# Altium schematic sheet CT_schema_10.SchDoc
size 387 x 278 mm
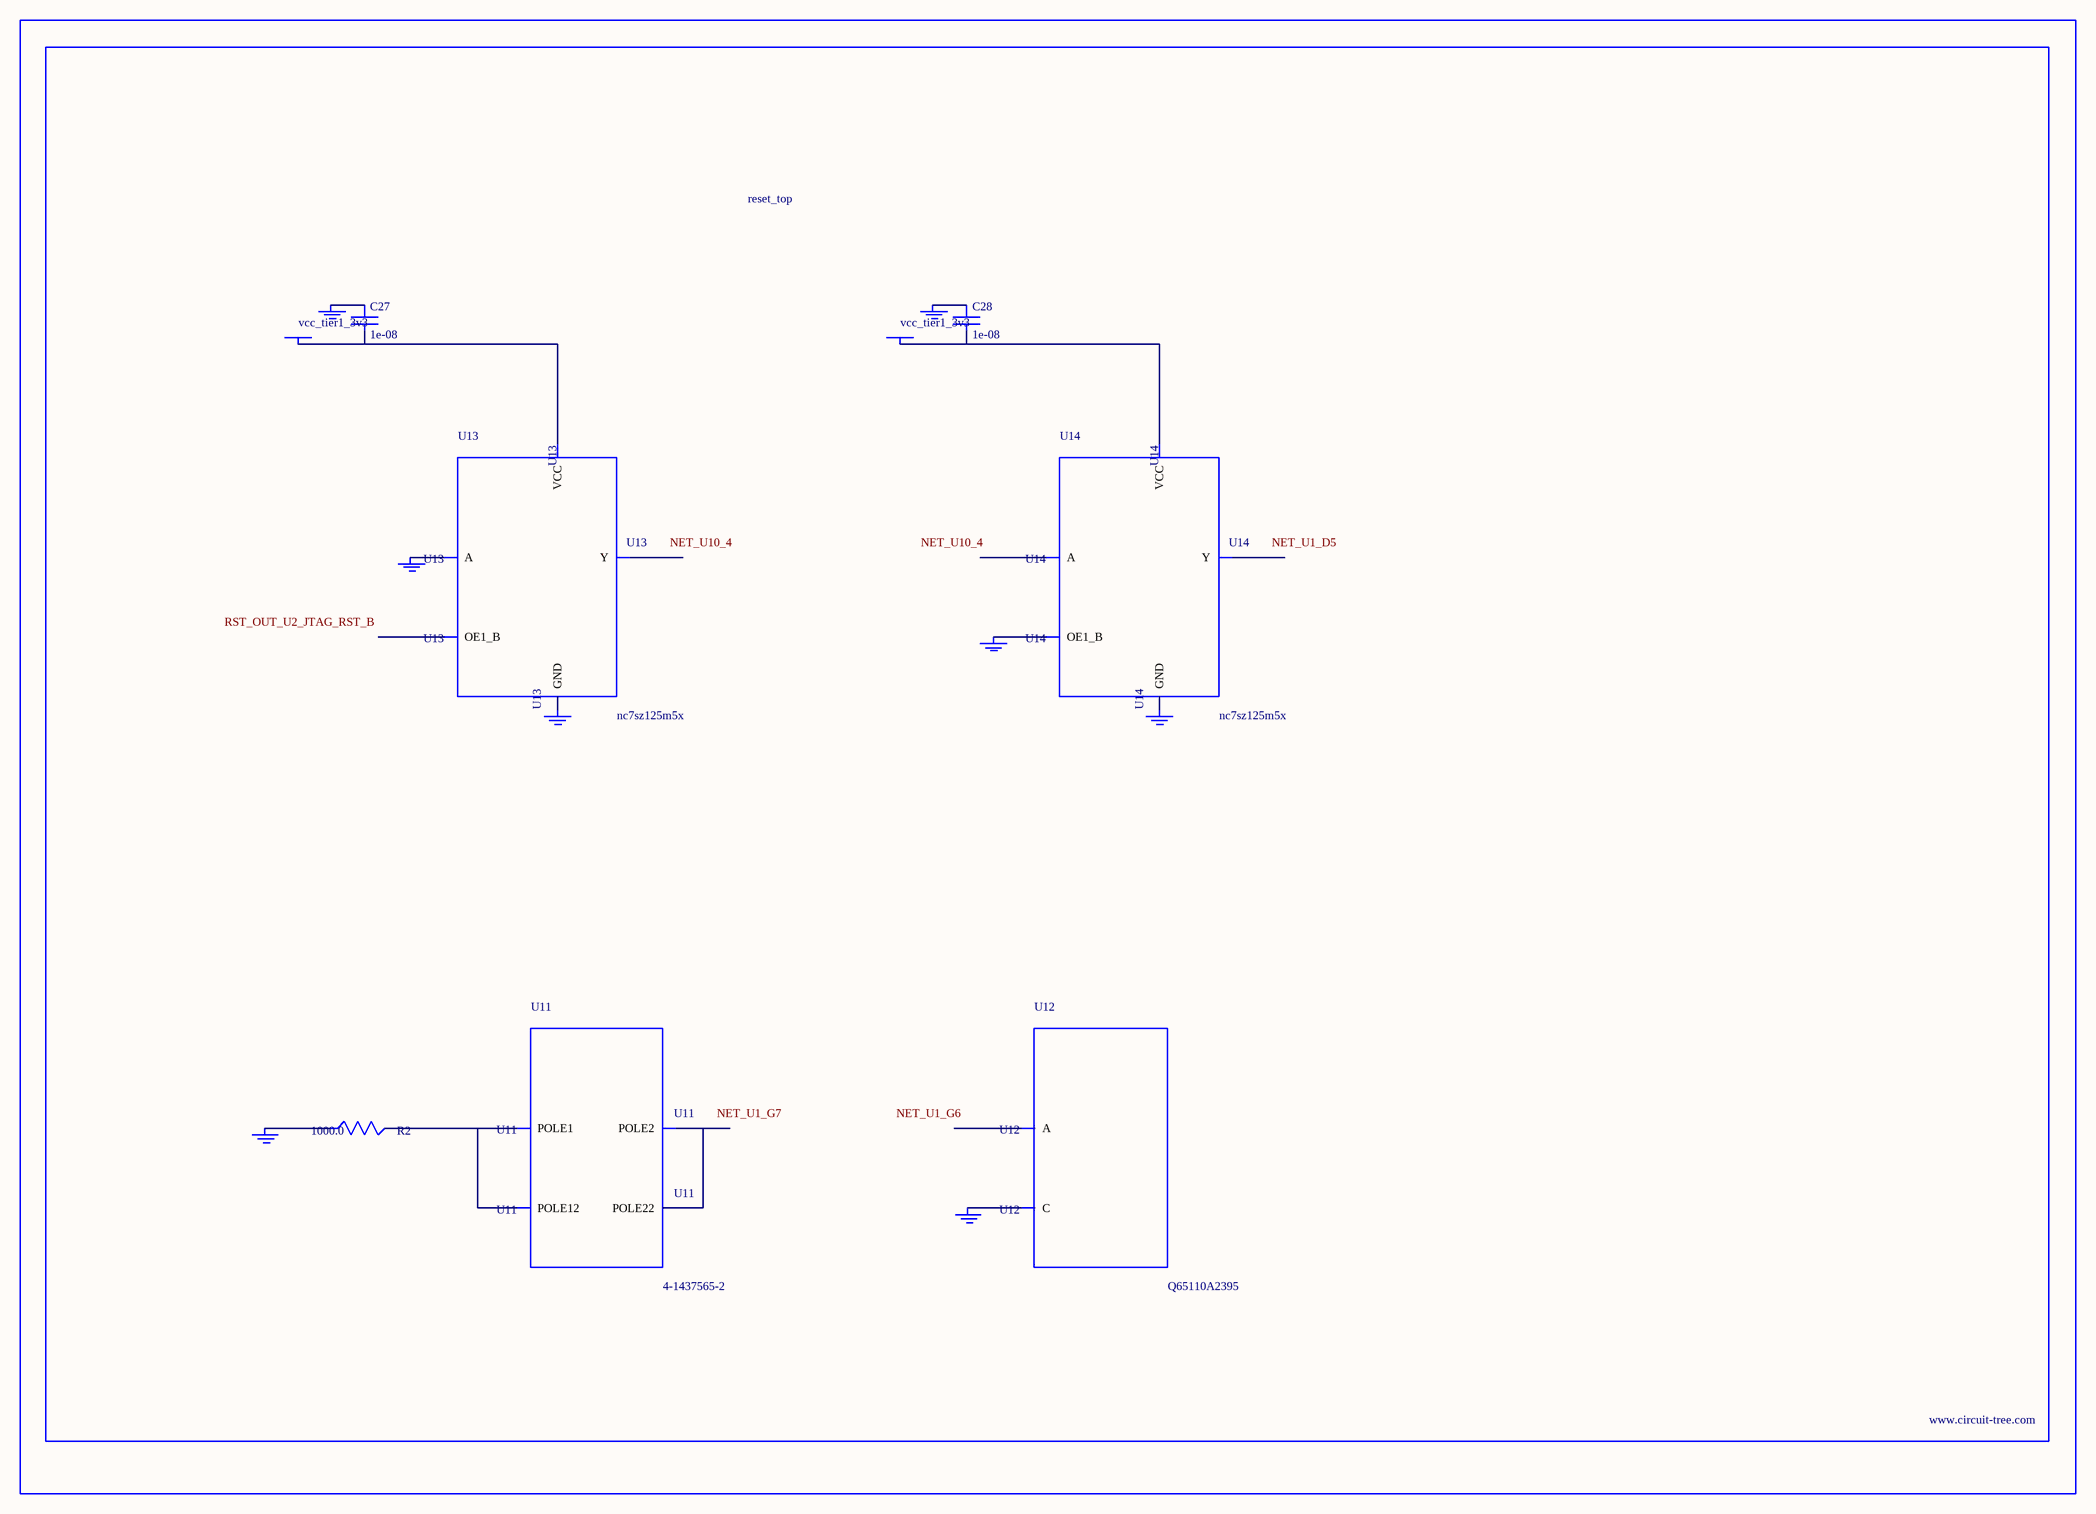
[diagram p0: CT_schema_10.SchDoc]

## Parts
BORDER9  (no value)
C27  1e-08  [C0402]
C28  1e-08  [C0402]
GND_INSTANCE_9_0  (no value)
GND_INSTANCE_9_1  (no value)
GND_INSTANCE_9_2  (no value)
GND_INSTANCE_9_3  (no value)
GND_INSTANCE_9_4  (no value)
GND_INSTANCE_9_5  (no value)
GND_INSTANCE_9_6  (no value)
GND_INSTANCE_9_7  (no value)
POWER_INSTANCE_9_0  vcc_tier1_3v3
POWER_INSTANCE_9_1  vcc_tier1_3v3
R2  1000.0  [R0603]
U11  4-1437565-2  [SW_4-1437565-2]
U12  Q65110A2395  [LGM67K-G1J2-24-Z]
U13  nc7sz125m5x  [NC7SZ125M5X]
U14  nc7sz125m5x  [NC7SZ125M5X]

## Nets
NetC27_1: C27.1 GND_INSTANCE_9_2.0(GND)
NetC27_2: C27.2 POWER_INSTANCE_9_0.0(PWR) U13.5(VCC)
NetC28_1: C28.1 GND_INSTANCE_9_5.0(GND)
NetC28_2: C28.2 POWER_INSTANCE_9_1.0(PWR) U14.5(VCC)
NetGND_INSTANCE_9_0_0: GND_INSTANCE_9_0.0(GND) R2.1
NetGND_INSTANCE_9_1_0: GND_INSTANCE_9_1.0(GND) U12.C
NetGND_INSTANCE_9_3_0: GND_INSTANCE_9_3.0(GND) U13.2(A)
NetGND_INSTANCE_9_4_0: GND_INSTANCE_9_4.0(GND) U13.3(GND)
NetGND_INSTANCE_9_6_0: GND_INSTANCE_9_6.0(GND) U14.1(OE1_B)
NetGND_INSTANCE_9_7_0: GND_INSTANCE_9_7.0(GND) U14.3(GND)
NetR2_2: R2.2 U11.1(POLE1) U11.2(POLE12)
NetU11_3: U11.3(POLE2) U11.4(POLE22)

Not connected (* = marked no-connect by the designer): U12 A; U13 1(OE1_B) 4(Y); U14 2(A) 4(Y)

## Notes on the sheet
- Labels drawn without touching a wire or pin: NET_U1_D5, NET_U1_G6, NET_U1_G7, NET_U10_4, RST_OUT_U2_JTAG_RST_B

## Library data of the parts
BORDER9 = BORDER_PAGE9
C27 C28 = C0402C103K3RAC
GND_INSTANCE_9_0-GND_INSTANCE_9_7 = GND
POWER_INSTANCE_9_0 POWER_INSTANCE_9_1 = PWR
R2 = RC0603JR-071KL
